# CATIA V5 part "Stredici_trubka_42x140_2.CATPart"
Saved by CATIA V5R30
Part number: Stredici_trubka_42x140_2
Definition: E 1160_42x140_1
Nomenclature: E 1160_42x140_1
Source: Unknown
Description: PART--DESC
Bounding box of the stored display mesh (mm): x 166 to 208, y 116.01 to 157.99, z -258 to -118
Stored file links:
  E:\Bakalarka\Model\Forma_v7\Stredici_trubka_42x140_2.CATPart
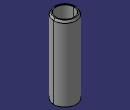
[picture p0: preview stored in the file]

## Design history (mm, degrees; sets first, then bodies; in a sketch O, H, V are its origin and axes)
Body1 "MANIFOLD_SOLID_BREP #3898" (main body)
  Solid1: solid without history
